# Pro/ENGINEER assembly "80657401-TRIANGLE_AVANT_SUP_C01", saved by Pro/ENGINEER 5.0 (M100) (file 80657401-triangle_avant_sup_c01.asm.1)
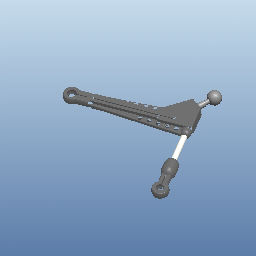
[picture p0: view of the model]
Units: millimeter Newton Second (mmNs); MM, TONNE, HOURS

Other components: 80657401-TRIANG_AV_SUP_C01, 80462600-ROTULE_D14_C01

Other named items: D-E, A-DROITE, A-DESSUS, A-FACE, A-R0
